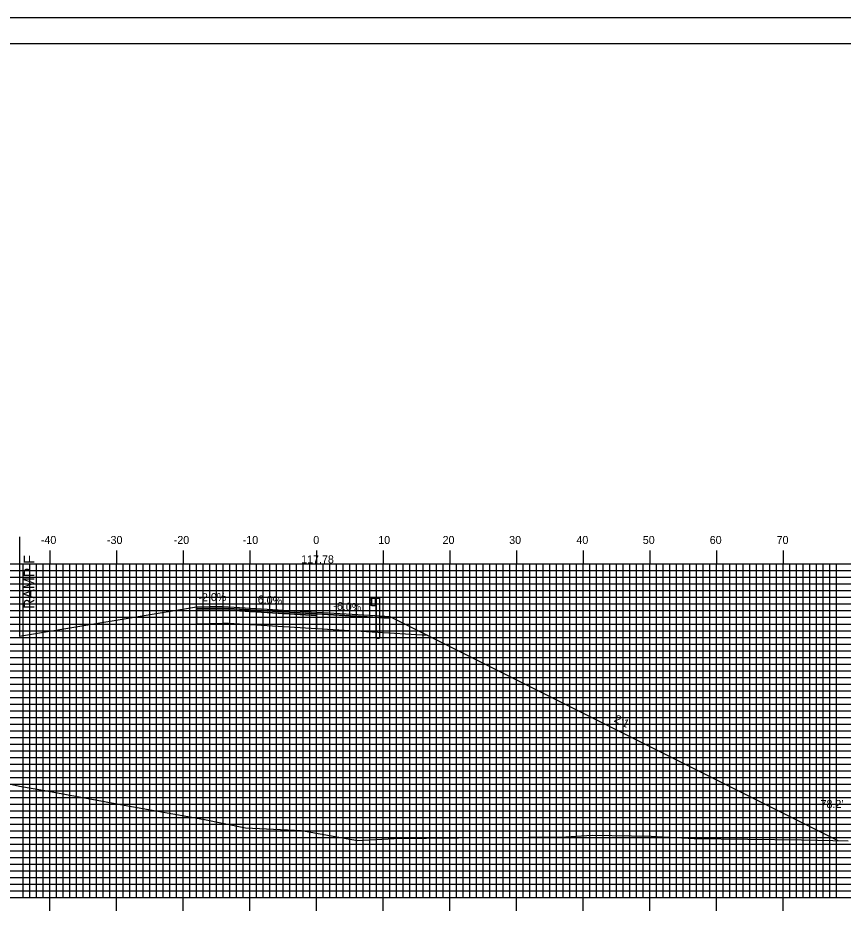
# Model space of a CAD drawing. Extents: x 856084 to 856427, y 364366 to 364586.
# Drawn here: x 856205 to 856328.8, y 364451.3 to 364585.7 of the extents above; entities that cross this region are included whole.
import ezdxf

# ---------------------------------------------------------------- set-up
doc = ezdxf.new("R2010")
doc.units = 0
for name, color, linetype in [('ANNOTATION', 7, 'Continuous'), ('BORDER', 7, 'Continuous'), ('D_Guardrail_Beam_Rt', 7, 'Continuous'), ('D_Roadway_Centerline', 7, 'Continuous'), ('D_Roadway_Centerline_Text', 7, 'Continuous'), ('D_Roadway_Edge_Shoulder', 7, 'Continuous'), ('D_Roadway_Edge_TW', 7, 'Continuous'), ('D_Roadway_Pavement', 7, 'Continuous'), ('D_Roadway_SlopeLines', 7, 'Continuous'), ('D_Roadway_SubGrade', 7, 'Continuous'), ('D_Text_Standard', 7, 'Continuous'), ('H_V ANNOTATION', 7, 'Continuous'), ('MAJOR', 7, 'Continuous'), ('MINOR', 7, 'Continuous'), ('PLOT BOUNDARY', 7, 'Continuous'), ('S_Roadway_Centerline', 7, 'Continuous')]:
    doc.layers.add(name, color=color, linetype=linetype)

msp = doc.modelspace()

# ---------------------------------------------------------------- linework, layer by layer
at = {"layer": 'BORDER'}
msp.add_lwpolyline([(856100.2, 364371.79), (856420.2, 364371.79), (856420.2, 364581.79), (856100.2, 364581.79)], close=True, dxfattribs=at)
at = {"layer": 'D_Guardrail_Beam_Rt'}
for p, q in [((856257.98, 364498.57), (856257.83, 364498.47)), ((856257.83, 364498.33), (856258.03, 364498.19)), ((856258.07, 364498.59), (856257.99, 364498.58)), ((856258.07, 364498.67), (856258.75, 364498.67)), ((856258.07, 364497.51), (856258.07, 364498.67)), ((856258.59, 364498.67), (856258.59, 364497.51)), ((856258.69, 364498.67), (856258.69, 364497.51)), ((856258.75, 364498.67), (856259.23, 364498.67)), ((856258.75, 364498.67), (856258.75, 364497.51)), ((856259.23, 364498.67), (856259.23, 364492.67)), ((856258.03, 364497.99), (856257.83, 364497.85)), ((856257.83, 364497.71), (856257.98, 364497.61)), ((856257.99, 364497.6), (856258.07, 364497.59)), ((856258.06, 364498.13), (856258.06, 364498.05)), ((856258.75, 364497.51), (856258.07, 364497.51)), ((856258.73, 364492.67), (856258.73, 364497.51)), ((856258.73, 364492.67), (856259.23, 364492.67))]:
    msp.add_line(p, q, dxfattribs=at)
for centre, major_axis, start_param, end_param in [((856257.88, 364498.4), (-0.0877, 0), 5.323254, 7.243116), ((856258, 364498.53), (-0.0417, 0), 4.907132, 5.323254), ((856257.88, 364497.78), (-0.0877, 0), 5.323254, 7.243116), ((856258, 364497.65), (-0.0417, 0), 0.959931, 1.376053), ((856257.98, 364498.13), (0.0789, 0), 0, 0.959931), ((856257.98, 364498.05), (0.0789, 0), 5.323254, 6.283185)]:
    msp.add_ellipse(centre, major_axis=major_axis, ratio=0.995501, start_param=start_param, end_param=end_param, dxfattribs=at)
at = {"layer": 'D_Roadway_Centerline'}
msp.add_lwpolyline([(856231.8, 364497.33), (856235.8, 364497.41), (856249.8, 364496.57), (856257.8, 364496.09), (856260.8, 364495.91), (856266.48, 364493.07), (856327.97, 364462.32)], dxfattribs=at)
at = {"layer": 'D_Roadway_Edge_Shoulder'}
for points in [[(856235.8, 364497.41), (856231.8, 364497.33), (856231.8, 364497.08), (856235.8, 364497.16)], [(856249.8, 364496.57), (856257.8, 364496.09), (856257.8, 364496.09), (856260.8, 364495.91), (856260.8, 364495.66), (856249.8, 364496.32)]]:
    msp.add_lwpolyline(points, close=True, dxfattribs=at)
at = {"layer": 'D_Roadway_Edge_TW'}
msp.add_lwpolyline([(856235.8, 364497.41), (856249.8, 364496.57), (856249.8, 364496.32), (856235.8, 364497.16)], close=True, dxfattribs=at)
at = {"layer": 'D_Roadway_Pavement'}
for points in [[(856235.8, 364497.16), (856231.8, 364497.08), (856231.8, 364496.83), (856235.8, 364496.91)], [(856235.8, 364497.16), (856249.8, 364496.32), (856249.8, 364496.07), (856235.8, 364496.91)]]:
    msp.add_lwpolyline(points, close=True, dxfattribs=at)
msp.add_lwpolyline([(856249.8, 364496.32), (856249.8, 364496.07)], dxfattribs=at)
msp.add_lwpolyline([(856249.8, 364496.32), (856249.8, 364496.07)], dxfattribs=at)
at = {"layer": 'D_Roadway_SlopeLines'}
for points in [[(856231.8, 364497.33), (856205.23, 364492.9)], [(856260.8, 364495.91), (856327.97, 364462.32)]]:
    msp.add_lwpolyline(points, dxfattribs=at)
at = {"layer": 'D_Roadway_SubGrade'}
msp.add_line((856205.23, 364507.86), (856205.23, 364492.9), dxfattribs=at)
for points in [[(856235.8, 364496.91), (856231.8, 364496.83), (856231.8, 364497.08), (856231.8, 364497.33), (856231.8, 364494.83), (856235.8, 364494.91)], [(856235.8, 364496.91), (856249.8, 364496.07), (856249.8, 364494.07), (856235.8, 364494.91)], [(856249.8, 364496.07), (856249.8, 364496.32), (856260.8, 364495.66), (856260.8, 364495.91), (856266.48, 364493.07), (856249.8, 364494.07)]]:
    msp.add_lwpolyline(points, close=True, dxfattribs=at)
at = {"layer": 'MAJOR'}
for p, q in [((856209.8, 364505.79), (856209.8, 364503.79)), ((856219.8, 364505.79), (856219.8, 364503.79)), ((856229.8, 364505.79), (856229.8, 364503.79)), ((856239.8, 364505.79), (856239.8, 364503.79)), ((856249.8, 364505.79), (856249.8, 364503.79)), ((856259.8, 364505.79), (856259.8, 364503.79)), ((856269.8, 364505.79), (856269.8, 364503.79)), ((856279.8, 364505.79), (856279.8, 364503.79)), ((856289.8, 364505.79), (856289.8, 364503.79)), ((856299.8, 364505.79), (856299.8, 364503.79)), ((856309.8, 364505.79), (856309.8, 364503.79)), ((856319.8, 364505.79), (856319.8, 364503.79)), ((856109.8, 364503.79), (856389.8, 364503.79)), ((856109.8, 364503.79), (856389.8, 364503.79)), ((856209.8, 364453.79), (856209.8, 364503.79)), ((856219.8, 364453.79), (856219.8, 364503.79)), ((856229.8, 364453.79), (856229.8, 364503.79)), ((856239.8, 364453.79), (856239.8, 364503.79)), ((856249.8, 364453.79), (856249.8, 364503.79)), ((856259.8, 364453.79), (856259.8, 364503.79)), ((856269.8, 364453.79), (856269.8, 364503.79)), ((856279.8, 364453.79), (856279.8, 364503.79)), ((856289.8, 364453.79), (856289.8, 364503.79)), ((856299.8, 364453.79), (856299.8, 364503.79)), ((856309.8, 364453.79), (856309.8, 364503.79)), ((856319.8, 364453.79), (856319.8, 364503.79)), ((856109.8, 364498.79), (856389.8, 364498.79)), ((856109.8, 364493.79), (856389.8, 364493.79)), ((856109.8, 364488.79), (856389.8, 364488.79)), ((856109.8, 364483.79), (856389.8, 364483.79)), ((856109.8, 364478.79), (856389.8, 364478.79)), ((856109.8, 364473.79), (856389.8, 364473.79)), ((856109.8, 364468.79), (856389.8, 364468.79)), ((856109.8, 364463.79), (856389.8, 364463.79)), ((856109.8, 364458.79), (856389.8, 364458.79)), ((856109.8, 364453.79), (856389.8, 364453.79)), ((856109.8, 364453.79), (856389.8, 364453.79)), ((856209.8, 364451.78), (856209.8, 364453.79)), ((856219.8, 364451.78), (856219.8, 364453.79)), ((856229.8, 364451.78), (856229.8, 364453.79)), ((856239.8, 364451.78), (856239.8, 364453.79)), ((856249.8, 364451.78), (856249.8, 364453.79)), ((856259.8, 364451.78), (856259.8, 364453.79)), ((856269.8, 364451.78), (856269.8, 364453.79)), ((856279.8, 364451.78), (856279.8, 364453.79)), ((856289.8, 364451.78), (856289.8, 364453.79)), ((856299.8, 364451.78), (856299.8, 364453.79)), ((856309.8, 364451.78), (856309.8, 364453.79)), ((856319.8, 364451.78), (856319.8, 364453.79))]:
    msp.add_line(p, q, dxfattribs=at)
at = {"layer": 'MINOR'}
for p, q in [((856205.8, 364453.79), (856205.8, 364503.79)), ((856206.8, 364453.79), (856206.8, 364503.79)), ((856207.8, 364453.79), (856207.8, 364503.79)), ((856208.8, 364453.79), (856208.8, 364503.79)), ((856210.8, 364453.79), (856210.8, 364503.79)), ((856211.8, 364453.79), (856211.8, 364503.79)), ((856212.8, 364453.79), (856212.8, 364503.79)), ((856213.8, 364453.79), (856213.8, 364503.79)), ((856214.8, 364453.79), (856214.8, 364503.79)), ((856215.8, 364453.79), (856215.8, 364503.79)), ((856216.8, 364453.79), (856216.8, 364503.79)), ((856217.8, 364453.79), (856217.8, 364503.79)), ((856218.8, 364453.79), (856218.8, 364503.79)), ((856220.8, 364453.79), (856220.8, 364503.79)), ((856221.8, 364453.79), (856221.8, 364503.79)), ((856222.8, 364453.79), (856222.8, 364503.79)), ((856223.8, 364453.79), (856223.8, 364503.79)), ((856224.8, 364453.79), (856224.8, 364503.79)), ((856225.8, 364453.79), (856225.8, 364503.79)), ((856226.8, 364453.79), (856226.8, 364503.79)), ((856227.8, 364453.79), (856227.8, 364503.79)), ((856228.8, 364453.79), (856228.8, 364503.79)), ((856230.8, 364453.79), (856230.8, 364503.79)), ((856231.8, 364453.79), (856231.8, 364503.79)), ((856232.8, 364453.79), (856232.8, 364503.79)), ((856233.8, 364453.79), (856233.8, 364503.79)), ((856234.8, 364453.79), (856234.8, 364503.79)), ((856235.8, 364453.79), (856235.8, 364503.79)), ((856236.8, 364453.79), (856236.8, 364503.79)), ((856237.8, 364453.79), (856237.8, 364503.79)), ((856238.8, 364453.79), (856238.8, 364503.79)), ((856240.8, 364453.79), (856240.8, 364503.79)), ((856241.8, 364453.79), (856241.8, 364503.79)), ((856242.8, 364453.79), (856242.8, 364503.79)), ((856243.8, 364453.79), (856243.8, 364503.79)), ((856244.8, 364453.79), (856244.8, 364503.79)), ((856245.8, 364453.79), (856245.8, 364503.79)), ((856246.8, 364453.79), (856246.8, 364503.79)), ((856247.8, 364453.79), (856247.8, 364503.79)), ((856248.8, 364453.79), (856248.8, 364503.79)), ((856250.8, 364453.79), (856250.8, 364503.79)), ((856251.8, 364453.79), (856251.8, 364503.79)), ((856252.8, 364453.79), (856252.8, 364503.79)), ((856253.8, 364453.79), (856253.8, 364503.79)), ((856254.8, 364453.79), (856254.8, 364503.79)), ((856255.8, 364453.79), (856255.8, 364503.79)), ((856256.8, 364453.79), (856256.8, 364503.79)), ((856257.8, 364453.79), (856257.8, 364503.79)), ((856258.8, 364453.79), (856258.8, 364503.79)), ((856260.8, 364453.79), (856260.8, 364503.79)), ((856261.8, 364453.79), (856261.8, 364503.79)), ((856262.8, 364453.79), (856262.8, 364503.79)), ((856263.8, 364453.79), (856263.8, 364503.79)), ((856264.8, 364453.79), (856264.8, 364503.79)), ((856265.8, 364453.79), (856265.8, 364503.79)), ((856266.8, 364453.79), (856266.8, 364503.79)), ((856267.8, 364453.79), (856267.8, 364503.79)), ((856268.8, 364453.79), (856268.8, 364503.79)), ((856270.8, 364453.79), (856270.8, 364503.79)), ((856271.8, 364453.79), (856271.8, 364503.79)), ((856272.8, 364453.79), (856272.8, 364503.79)), ((856273.8, 364453.79), (856273.8, 364503.79)), ((856274.8, 364453.79), (856274.8, 364503.79)), ((856275.8, 364453.79), (856275.8, 364503.79)), ((856276.8, 364453.79), (856276.8, 364503.79)), ((856277.8, 364453.79), (856277.8, 364503.79)), ((856278.8, 364453.79), (856278.8, 364503.79)), ((856280.8, 364453.79), (856280.8, 364503.79)), ((856281.8, 364453.79), (856281.8, 364503.79)), ((856282.8, 364453.79), (856282.8, 364503.79)), ((856283.8, 364453.79), (856283.8, 364503.79)), ((856284.8, 364453.79), (856284.8, 364503.79)), ((856285.8, 364453.79), (856285.8, 364503.79)), ((856286.8, 364453.79), (856286.8, 364503.79)), ((856287.8, 364453.79), (856287.8, 364503.79)), ((856288.8, 364453.79), (856288.8, 364503.79)), ((856290.8, 364453.79), (856290.8, 364503.79)), ((856291.8, 364453.79), (856291.8, 364503.79)), ((856292.8, 364453.79), (856292.8, 364503.79)), ((856293.8, 364453.79), (856293.8, 364503.79)), ((856294.8, 364453.79), (856294.8, 364503.79)), ((856295.8, 364453.79), (856295.8, 364503.79)), ((856296.8, 364453.79), (856296.8, 364503.79)), ((856297.8, 364453.79), (856297.8, 364503.79)), ((856298.8, 364453.79), (856298.8, 364503.79)), ((856300.8, 364453.79), (856300.8, 364503.79)), ((856301.8, 364453.79), (856301.8, 364503.79)), ((856302.8, 364453.79), (856302.8, 364503.79)), ((856303.8, 364453.79), (856303.8, 364503.79)), ((856304.8, 364453.79), (856304.8, 364503.79)), ((856305.8, 364453.79), (856305.8, 364503.79)), ((856306.8, 364453.79), (856306.8, 364503.79)), ((856307.8, 364453.79), (856307.8, 364503.79)), ((856308.8, 364453.79), (856308.8, 364503.79)), ((856310.8, 364453.79), (856310.8, 364503.79)), ((856311.8, 364453.79), (856311.8, 364503.79)), ((856312.8, 364453.79), (856312.8, 364503.79)), ((856313.8, 364453.79), (856313.8, 364503.79)), ((856314.8, 364453.79), (856314.8, 364503.79)), ((856315.8, 364453.79), (856315.8, 364503.79)), ((856316.8, 364453.79), (856316.8, 364503.79)), ((856317.8, 364453.79), (856317.8, 364503.79)), ((856318.8, 364453.79), (856318.8, 364503.79)), ((856320.8, 364453.79), (856320.8, 364503.79)), ((856321.8, 364453.79), (856321.8, 364503.79)), ((856322.8, 364453.79), (856322.8, 364503.79)), ((856323.8, 364453.79), (856323.8, 364503.79)), ((856324.8, 364453.79), (856324.8, 364503.79)), ((856325.8, 364453.79), (856325.8, 364503.79)), ((856326.8, 364453.79), (856326.8, 364503.79)), ((856327.8, 364453.79), (856327.8, 364503.79)), ((856109.8, 364502.79), (856389.8, 364502.79)), ((856109.8, 364501.79), (856389.8, 364501.79)), ((856109.8, 364500.79), (856389.8, 364500.79)), ((856109.8, 364499.79), (856389.8, 364499.79)), ((856109.8, 364497.79), (856389.8, 364497.79)), ((856109.8, 364496.79), (856389.8, 364496.79)), ((856109.8, 364495.79), (856389.8, 364495.79)), ((856109.8, 364494.79), (856389.8, 364494.79)), ((856109.8, 364492.79), (856389.8, 364492.79)), ((856109.8, 364491.79), (856389.8, 364491.79)), ((856109.8, 364490.79), (856389.8, 364490.79)), ((856109.8, 364489.79), (856389.8, 364489.79)), ((856109.8, 364487.79), (856389.8, 364487.79)), ((856109.8, 364486.79), (856389.8, 364486.79)), ((856109.8, 364485.79), (856389.8, 364485.79)), ((856109.8, 364484.79), (856389.8, 364484.79)), ((856109.8, 364482.79), (856389.8, 364482.79)), ((856109.8, 364481.79), (856389.8, 364481.79)), ((856109.8, 364480.79), (856389.8, 364480.79)), ((856109.8, 364479.79), (856389.8, 364479.79)), ((856109.8, 364477.79), (856389.8, 364477.79)), ((856109.8, 364476.79), (856389.8, 364476.79)), ((856109.8, 364475.79), (856389.8, 364475.79)), ((856109.8, 364474.79), (856389.8, 364474.79)), ((856109.8, 364472.79), (856389.8, 364472.79)), ((856109.8, 364471.79), (856389.8, 364471.79)), ((856109.8, 364470.79), (856389.8, 364470.79)), ((856109.8, 364469.79), (856389.8, 364469.79)), ((856109.8, 364467.79), (856389.8, 364467.79)), ((856109.8, 364466.79), (856389.8, 364466.79)), ((856109.8, 364465.79), (856389.8, 364465.79)), ((856109.8, 364464.79), (856389.8, 364464.79)), ((856109.8, 364462.79), (856389.8, 364462.79)), ((856109.8, 364461.79), (856389.8, 364461.79)), ((856109.8, 364460.79), (856389.8, 364460.79)), ((856109.8, 364459.79), (856389.8, 364459.79)), ((856109.8, 364457.79), (856389.8, 364457.79)), ((856109.8, 364456.79), (856389.8, 364456.79)), ((856109.8, 364455.79), (856389.8, 364455.79)), ((856109.8, 364454.79), (856389.8, 364454.79))]:
    msp.add_line(p, q, dxfattribs=at)
at = {"layer": 'PLOT BOUNDARY'}
msp.add_lwpolyline([(856084.01, 364365.67), (856424.01, 364365.67), (856424.01, 364585.67), (856084.01, 364585.67)], close=True, dxfattribs=at)
at = {"layer": 'S_Roadway_Centerline'}
msp.add_lwpolyline([(856196.61, 364472.4), (856205.25, 364470.46), (856209.04, 364469.81), (856221.52, 364467.5), (856232.76, 364465.53), (856239.15, 364464.21), (856247.52, 364463.83), (856255.95, 364462.31), (856261.43, 364462.61), (856275.95, 364462.76), (856287.18, 364462.87), (856291.15, 364463.12), (856300, 364462.96), (856306.44, 364462.64), (856322.52, 364462.43), (856324.92, 364462.38), (856329.55, 364462.29)], dxfattribs=at)

# ---------------------------------------------------------------- texts
at = {"layer": 'ANNOTATION'}
for s, height, rotation, p in [('RAMP F', 1.6, 90, (856207.49, 364497.04)), ('-2.0%', 1.2, 1.1458, (856232.09, 364498.18)), ('6.0%', 1.2, 356.5664, (856240.95, 364497.9)), ('-6.0%', 1.2, 356.5664, (856252.29, 364496.94)), ('2:1', 1.2, 333.4349, (856294.32, 364480.19))]:
    msp.add_text(s, height=height, rotation=rotation, dxfattribs=at).set_placement(p)
at = {"layer": 'D_Roadway_Centerline_Text'}
msp.add_text('117.78', height=1.2, dxfattribs=at).set_placement((856247.49, 364503.89))
at = {"layer": 'D_Text_Standard'}
msp.add_text("78.2'", height=1.2, dxfattribs=at).set_placement((856325.39, 364467.2))
at = {"layer": 'H_V ANNOTATION'}
for s, p in [('-40', (856208.45, 364506.79)), ('-30', (856218.37, 364506.79)), ('-20', (856228.38, 364506.79)), ('-10', (856238.73, 364506.79)), ('0', (856249.31, 364506.79)), ('10', (856259.05, 364506.79)), ('20', (856268.7, 364506.79)), ('30', (856278.69, 364506.79)), ('40', (856288.77, 364506.79)), ('50', (856298.73, 364506.79)), ('60', (856308.77, 364506.79)), ('70', (856318.8, 364506.79))]:
    msp.add_text(s, height=1.2, dxfattribs=at).set_placement(p)

doc.saveas('drawing.dxf')
